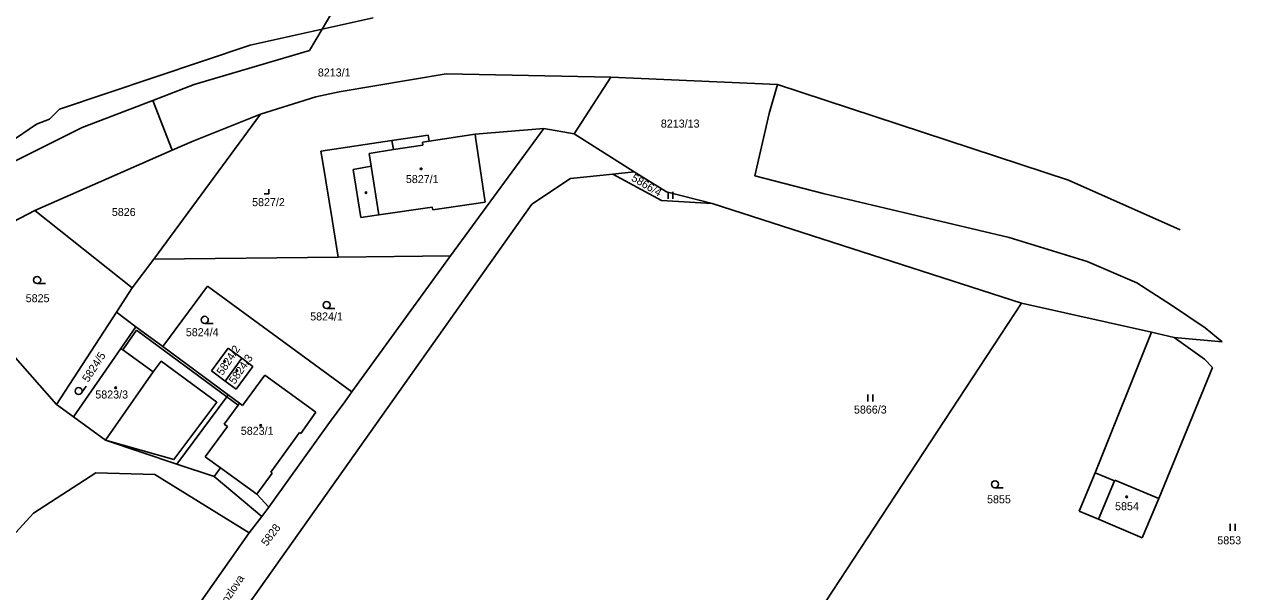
# Model space of a CAD drawing. Extents: x -717507 to -715515, y -957700 to -954941.
# Drawn here: x -715773.2 to -715514.7, y -955222.4 to -955101.9 of the extents above; entities that cross this region are included whole.
import ezdxf

# ---------------------------------------------------------------- set-up
doc = ezdxf.new("R2010")
doc.units = 0
for name, color, linetype in [('Hranice parcel', 7, 'Continuous'), ('Parcelní čísla', 7, 'Continuous'), ('Pop  PČ popisy', 7, 'Continuous'), ('Vnitřní kresba', 7, 'Continuous'), ('Značky budov', 7, 'Continuous'), ('Značky kultur', 7, 'Continuous')]:
    doc.layers.add(name, color=color, linetype=linetype)

msp = doc.modelspace()

# ---------------------------------------------------------------- linework, layer by layer
at = {"layer": 'Hranice parcel'}
for points in [[(-715709.87, -955102.92), (-715707.14, -955098.25)], [(-715709.87, -955102.92), (-715699.09, -955100.5)], [(-715712.55, -955107.48), (-715709.87, -955102.92)], [(-715737.09, -955114.71), (-715712.55, -955107.48)], [(-715706.27, -955116.24), (-715683.56, -955112.45)], [(-715683.56, -955112.45), (-715648.53, -955113.15)], [(-715745.86, -955118.06), (-715737.09, -955114.71)], [(-715656.36, -955125.15), (-715648.53, -955113.15)], [(-715613.16, -955114.68), (-715648.53, -955113.15)], [(-715613.16, -955114.68), (-715614.94, -955120.84)], [(-715613.16, -955114.68), (-715551.29, -955134.97)], [(-715723.02, -955120.97), (-715711.24, -955117.28)], [(-715711.24, -955117.28), (-715706.27, -955116.24)], [(-715760.9, -955123.82), (-715745.86, -955118.06)], [(-715745.86, -955118.06), (-715741.78, -955128.65)], [(-715745.67, -955151.75), (-715723.02, -955120.97)], [(-715737.53, -955126.78), (-715723.02, -955120.97)], [(-715614.94, -955120.84), (-715617.98, -955134.09)], [(-715786.91, -955136.74), (-715760.9, -955123.82)], [(-715695.08, -955126.59), (-715687.38, -955125.45)], [(-715687.38, -955125.45), (-715687.18, -955126.75)], [(-715687.18, -955126.75), (-715677.38, -955125.25)], [(-715682.6, -955151.07), (-715662.77, -955124)], [(-715677.38, -955125.25), (-715662.77, -955124)], [(-715662.77, -955124), (-715656.36, -955125.15)], [(-715656.36, -955125.15), (-715643.58, -955133.26)], [(-715741.78, -955128.65), (-715737.53, -955126.78)], [(-715710.15, -955128.81), (-715695.08, -955126.59)], [(-715770.94, -955141.43), (-715741.78, -955128.65)], [(-715710.15, -955128.81), (-715709.83, -955130.82)], [(-715709.83, -955130.82), (-715707.73, -955143.8)], [(-715648.15, -955133.72), (-715643.58, -955133.26)], [(-715643.58, -955133.26), (-715636.71, -955137.49)], [(-715665.35, -955140.11), (-715657.13, -955134.64)], [(-715657.13, -955134.64), (-715648.15, -955133.72)], [(-715648.15, -955133.72), (-715637.81, -955139.28)], [(-715617.98, -955134.09), (-715603.41, -955137.8)], [(-715551.29, -955134.97), (-715527.6, -955145.52)], [(-715636.71, -955137.49), (-715627.05, -955139.97)], [(-715603.41, -955137.8), (-715563.91, -955147.17)], [(-715738.6, -955243.39), (-715665.35, -955140.11)], [(-715637.81, -955139.28), (-715627.05, -955139.97)], [(-715627.05, -955139.97), (-715561.27, -955161.1)], [(-715792.68, -955152.77), (-715770.94, -955141.43)], [(-715770.94, -955141.43), (-715750.25, -955157.88)], [(-715707.73, -955143.8), (-715706.52, -955151.33)], [(-715563.91, -955147.17), (-715547.35, -955152.23)], [(-715745.67, -955151.75), (-715706.52, -955151.33)], [(-715706.52, -955151.33), (-715682.6, -955151.07)], [(-715703.59, -955179.94), (-715682.6, -955151.07)], [(-715792.68, -955152.77), (-715766.36, -955182.61)], [(-715750.25, -955157.88), (-715745.67, -955151.75)], [(-715536.77, -955156.77), (-715547.35, -955152.23)], [(-715753.62, -955163.05), (-715750.25, -955157.88)], [(-715734.27, -955157.51), (-715743.76, -955170.34)], [(-715703.59, -955179.94), (-715734.27, -955157.51)], [(-715529.4, -955161.54), (-715536.77, -955156.77)], [(-715613.34, -955240.35), (-715561.27, -955161.1)], [(-715561.27, -955161.1), (-715533.69, -955167.3)], [(-715522.27, -955166.37), (-715529.4, -955161.54)], [(-715766.36, -955182.61), (-715753.62, -955163.05)], [(-715753.62, -955163.05), (-715749.45, -955166.13)], [(-715752.64, -955170.72), (-715749.45, -955166.13)], [(-715749.45, -955166.13), (-715743.76, -955170.34)], [(-715518.65, -955169.3), (-715522.27, -955166.37)], [(-715545.64, -955197.13), (-715533.69, -955167.3)], [(-715533.69, -955167.3), (-715528.83, -955168.42)], [(-715528.83, -955168.42), (-715522.42, -955172.99)], [(-715528.83, -955168.42), (-715518.65, -955169.3)], [(-715762.74, -955185.26), (-715752.64, -955170.72)], [(-715743.76, -955170.34), (-715729.89, -955180.58)], [(-715733.43, -955175.46), (-715729.87, -955170.64)], [(-715729.87, -955170.64), (-715726.94, -955172.8)], [(-715730.5, -955177.65), (-715726.94, -955172.8)], [(-715728.17, -955179.39), (-715724.59, -955174.54)], [(-715726.94, -955172.8), (-715724.59, -955174.54)], [(-715532.13, -955202.59), (-715520.72, -955174.78)], [(-715522.42, -955172.99), (-715520.72, -955174.78)], [(-715733.43, -955175.46), (-715730.5, -955177.65)], [(-715726.79, -955182.87), (-715722.05, -955176.37)], [(-715722.05, -955176.37), (-715711.24, -955184.26)], [(-715730.5, -955177.65), (-715728.17, -955179.39)], [(-715705.11, -955182.03), (-715703.59, -955179.94)], [(-715730.18, -955180.98), (-715740.74, -955195.28)], [(-715729.89, -955180.58), (-715730.18, -955180.98)], [(-715729.89, -955180.58), (-715727.47, -955182.37)], [(-715727.47, -955182.37), (-715726.79, -955182.87)], [(-715708.31, -955186.44), (-715705.11, -955182.03)], [(-715766.36, -955182.61), (-715762.74, -955185.26)], [(-715714.46, -955188.76), (-715711.24, -955184.26)], [(-715762.74, -955185.26), (-715755.93, -955190.21)], [(-715720.14, -955202.97), (-715708.31, -955186.44)], [(-715755.93, -955190.21), (-715740.74, -955195.28)], [(-715720.78, -955197.01), (-715714.7, -955188.58)], [(-715714.7, -955188.58), (-715714.46, -955188.76)], [(-715740.74, -955195.28), (-715732.82, -955197.92)], [(-715771.23, -955205.7), (-715757.95, -955197.12)], [(-715757.95, -955197.12), (-715745.47, -955197.47)], [(-715745.47, -955197.47), (-715725.4, -955209.9)], [(-715732.82, -955197.92), (-715722.74, -955206.39)], [(-715723.74, -955201.64), (-715720.53, -955197.19)], [(-715720.78, -955197.01), (-715720.53, -955197.19)], [(-715549.05, -955205.26), (-715545.64, -955197.13)], [(-715723.74, -955201.64), (-715721.23, -955204.41)], [(-715721.23, -955204.41), (-715720.14, -955202.97)], [(-715535.63, -955210.94), (-715532.13, -955202.59)], [(-715793.97, -955230.46), (-715771.23, -955205.7)], [(-715722.74, -955206.39), (-715721.23, -955204.41)], [(-715549.05, -955205.26), (-715544.91, -955206.99)], [(-715725.4, -955209.9), (-715722.74, -955206.39)], [(-715544.91, -955206.99), (-715535.63, -955210.94)], [(-715751.32, -955246.77), (-715725.4, -955209.9)]]:
    msp.add_lwpolyline(points, dxfattribs=at)
at = {"layer": 'Vnitřní kresba'}
for points in [[(-715725.16, -955106.35), (-715709.87, -955102.92)], [(-715765.72, -955119.92), (-715725.16, -955106.35)], [(-715767.86, -955122.05), (-715765.72, -955119.92)], [(-715835.08, -955167.05), (-715770.62, -955123.08)], [(-715770.62, -955123.08), (-715767.86, -955122.05)], [(-715677.38, -955125.25), (-715677.29, -955125.84)], [(-715695.08, -955126.59), (-715694.71, -955128.51)], [(-715694.71, -955128.51), (-715688.49, -955127.56)], [(-715688.59, -955126.96), (-715687.18, -955126.75)], [(-715688.59, -955126.96), (-715688.49, -955127.56)], [(-715677.29, -955125.84), (-715675.23, -955139.69)], [(-715699.9, -955129.3), (-715694.71, -955128.51)], [(-715699.9, -955129.3), (-715699.47, -955132.04)], [(-715703.28, -955132.7), (-715699.47, -955132.04)], [(-715703.28, -955132.7), (-715701.7, -955142.93)], [(-715699.47, -955132.04), (-715697.84, -955142.37)], [(-715697.84, -955142.37), (-715686.5, -955140.73)], [(-715686.5, -955140.73), (-715686.41, -955141.3)], [(-715686.41, -955141.3), (-715675.23, -955139.69)], [(-715701.7, -955142.93), (-715697.84, -955142.37)], [(-715752.23, -955171.02), (-715749.32, -955166.83)], [(-715749.32, -955166.83), (-715730.18, -955180.98)], [(-715752.64, -955170.72), (-715752.23, -955171.02)], [(-715752.23, -955171.02), (-715745.78, -955175.71)], [(-715755.93, -955190.21), (-715741.39, -955194.32), (-715732.3, -955182.14), (-715744.09, -955173.45), (-715745.78, -955175.71)], [(-715755.93, -955190.21), (-715745.78, -955175.71)], [(-715730.18, -955180.98), (-715727.77, -955182.77)], [(-715727.77, -955182.77), (-715727.47, -955182.37)], [(-715730.71, -955186.77), (-715727.77, -955182.77)], [(-715734.72, -955193.77), (-715730, -955187.29)], [(-715730.71, -955186.77), (-715730, -955187.29)], [(-715734.72, -955193.77), (-715731.5, -955196.08)], [(-715732.82, -955197.92), (-715731.5, -955196.08)], [(-715731.5, -955196.08), (-715723.74, -955201.64)], [(-715545.64, -955197.13), (-715541.51, -955198.86)], [(-715544.91, -955206.99), (-715541.51, -955198.86)], [(-715541.51, -955198.86), (-715541.44, -955198.69)], [(-715541.44, -955198.69), (-715532.13, -955202.59)]]:
    msp.add_lwpolyline(points, dxfattribs=at)
at = {"layer": 'Značky budov'}
for centre in [(-715688.87, -955132.59), (-715700.59, -955137.66), (-715730.64, -955173.49), (-715728.01, -955175.43), (-715753.78, -955179.07), (-715722.97, -955187.06), (-715538.96, -955202.24)]:
    msp.add_circle(centre, 0.175, dxfattribs=at)
at = {"layer": 'Značky kultur'}
for points in [[(-715722.23, -955137.91), (-715721.23, -955137.91), (-715721.23, -955136.91)], [(-715636.41, -955138.95), (-715636.41, -955137.45)], [(-715635.37, -955138.95), (-715635.37, -955137.45)], [(-715770.45, -955156.95), (-715768.7, -955156.95)], [(-715708.95, -955162.25), (-715707.2, -955162.25)], [(-715734.83, -955165.4), (-715733.08, -955165.4)], [(-715761.01, -955180.18), (-715760.05, -955178.71)], [(-715593.93, -955182.02), (-715593.93, -955180.52)], [(-715592.89, -955182.02), (-715592.89, -955180.52)], [(-715566.94, -955200.31), (-715565.19, -955200.31)], [(-715516.96, -955209.44), (-715516.96, -955207.94)], [(-715515.92, -955209.44), (-715515.92, -955207.94)]]:
    msp.add_lwpolyline(points, dxfattribs=at)
for centre, radius in [((-715770.45, -955156.2), 0.75), ((-715708.95, -955161.5), 0.75), ((-715734.83, -955164.65), 0.75), ((-715761.64, -955179.77), 0.749), ((-715566.94, -955199.56), 0.75)]:
    msp.add_circle(centre, radius, dxfattribs=at)

# ---------------------------------------------------------------- texts
at = {"layer": 'Parcelní čísla'}
for s, p in [('8213/1', (-715710.81, -955112.98)), ('8213/13', (-715637.93, -955123.83)), ('5827/1', (-715692.11, -955135.61)), ('5826', (-715754.58, -955142.6)), ('5827/2', (-715724.78, -955140.51)), ('5825', (-715772.88, -955160.91)), ('5824/1', (-715712.44, -955164.78)), ('5824/4', (-715738.86, -955168.12)), ('5823/3', (-715758.09, -955181.35)), ('5866/3', (-715596.9, -955184.55)), ('5823/1', (-715727.18, -955189.06)), ('5855', (-715568.62, -955203.6)), ('5854', (-715541.42, -955205.07)), ('5853', (-715519.69, -955212.31))]:
    msp.add_text(s, height=1.7, dxfattribs=at).set_placement(p)
for s, rotation, p in [('5866/4', 329.4026, (-715644.36, -955135)), ('5824/5', 56.9005, (-715759.6, -955178.02)), ('5824/2', 56.5005, (-715731.05, -955176.58)), ('5824/3', 55.4004, (-715728.47, -955178.45)), ('5828', 53.4004, (-715721.64, -955212.83))]:
    msp.add_text(s, height=1.7, rotation=rotation, dxfattribs=at).set_placement(p)
at = {"layer": 'Pop  PČ popisy'}
msp.add_text('Kozlova', height=1.7, rotation=56.1004, dxfattribs=at).set_placement((-715730.87, -955226.22))

doc.saveas('drawing.dxf')
